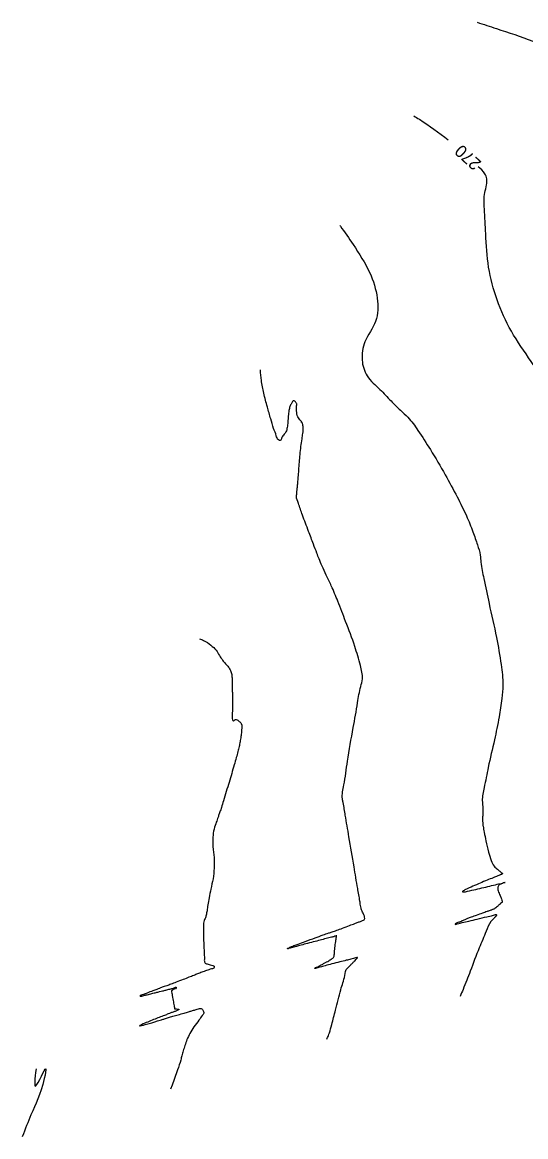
# Model space of a CAD drawing. Extents: x -478102 to -473059, y -1117705 to -1114104.
# Drawn here: x -478101.7 to -477938.7, y -1117550.7 to -1117189.8 of the extents above; entities that cross this region are included whole.
import ezdxf

# ---------------------------------------------------------------- set-up
doc = ezdxf.new("R2010")
doc.units = 0
for name, color, linetype in [('Vrstevnice_hlavni', 7, 'Continuous'), ('Vrstevnice_popis', 7, 'Continuous'), ('Vrstevnice_vedlejsi', 7, 'Continuous')]:
    doc.layers.add(name, color=color, linetype=linetype)

msp = doc.modelspace()

# ---------------------------------------------------------------- linework, layer by layer
at = {"layer": 'Vrstevnice_hlavni'}
for points in [[(-477974.913, -1117220.071), (-477973.154, -1117221.178), (-477963.793, -1117227.865)], [(-477911.583, -1117449.228), (-477910.477, -1117445.772), (-477910.019, -1117444.447), (-477909.658, -1117443.526), (-477909.392, -1117443.009), (-477909.13, -1117442.624), (-477908.873, -1117442.372), (-477908.621, -1117442.252), (-477908.32, -1117440.177), (-477907.97, -1117436.148), (-477907.573, -1117430.164), (-477907.024, -1117423.487), (-477906.324, -1117416.119), (-477905.473, -1117408.06), (-477904.757, -1117400.83), (-477904.178, -1117394.43), (-477903.734, -1117388.86), (-477903.684, -1117382.559), (-477904.026, -1117375.527), (-477904.762, -1117367.764), (-477905.619, -1117361.343), (-477906.598, -1117356.266), (-477907.698, -1117352.532), (-477909.68, -1117347.951), (-477912.544, -1117342.521), (-477916.289, -1117336.243), (-477919.3, -1117330.94), (-477921.576, -1117326.612), (-477923.119, -1117323.257), (-477924.801, -1117319.855), (-477926.621, -1117316.406), (-477928.579, -1117312.91), (-477932.023, -1117307.311), (-477936.953, -1117299.609), (-477943.367, -1117289.805), (-477947.957, -1117279.645), (-477950.723, -1117269.132), (-477951.664, -1117258.263), (-477952.088, -1117250.196), (-477951.996, -1117244.93), (-477951.386, -1117242.465), (-477951.356, -1117240.437), (-477951.906, -1117238.846), (-477954.163, -1117236.539)]]:
    msp.add_spline(points, degree=3, dxfattribs=at)
at = {"layer": 'Vrstevnice_vedlejsi'}
msp.add_line((-478053.213, -1117534.03), (-478053.687, -1117535.309), dxfattribs=at)
for points in [[(-477954.454, -1117189.777), (-477948.211, -1117191.791), (-477936.422, -1117195.896), (-477928.048, -1117199.17), (-477923.089, -1117201.613), (-477921.545, -1117203.226), (-477918.986, -1117206.68), (-477915.414, -1117211.974), (-477910.828, -1117219.108), (-477907.487, -1117225.392), (-477905.391, -1117230.828), (-477904.539, -1117235.414), (-477904.79, -1117241.921), (-477906.143, -1117250.35), (-477908.597, -1117260.701), (-477910.296, -1117268.595), (-477911.24, -1117274.034), (-477911.429, -1117277.017), (-477909.757, -1117280.714), (-477906.224, -1117285.125), (-477900.83, -1117290.251), (-477895.519, -1117295.224), (-477890.29, -1117300.046), (-477885.145, -1117304.716), (-477880.549, -1117309.008), (-477876.503, -1117312.924), (-477873.006, -1117316.462), (-477870.428, -1117320.233), (-477868.77, -1117324.236), (-477868.031, -1117328.472), (-477866.681, -1117334.328), (-477864.72, -1117341.805), (-477862.147, -1117350.902), (-477860.639, -1117359.029), (-477860.198, -1117366.184), (-477860.823, -1117372.368), (-477861.454, -1117378.874), (-477862.091, -1117385.702), (-477862.734, -1117392.851), (-477863.037, -1117399.446), (-477862.998, -1117405.488), (-477862.617, -1117410.976), (-477862.345, -1117415.865), (-477862.18, -1117420.156), (-477862.122, -1117423.848), (-477862.019, -1117426.978), (-477861.868, -1117429.545), (-477861.672, -1117431.549), (-477861.33, -1117433.074), (-477860.844, -1117434.119), (-477860.213, -1117434.684), (-477859.737, -1117435.119), (-477859.415, -1117435.425), (-477859.249, -1117435.601), (-477859.805, -1117436.002), (-477861.085, -1117436.629), (-477863.088, -1117437.481), (-477864.741, -1117438.177), (-477866.043, -1117438.717), (-477866.996, -1117439.1), (-477868.438, -1117439.714), (-477870.371, -1117440.557), (-477872.793, -1117441.629), (-477874.666, -1117442.446), (-477875.99, -1117443.008), (-477876.763, -1117443.314), (-477877.55, -1117443.633), (-477878.351, -1117443.965), (-477879.164, -1117444.31), (-477879.357, -1117444.451), (-477878.928, -1117444.387), (-477877.878, -1117444.12), (-477877.052, -1117443.907), (-477876.449, -1117443.747), (-477876.07, -1117443.642), (-477874.783, -1117443.296), (-477872.588, -1117442.71)], [(-477998.879, -1117255.557), (-477998.727, -1117255.77), (-477994.613, -1117261.766), (-477989.226, -1117270.883), (-477986.788, -1117279.171), (-477987.299, -1117286.631), (-477990.759, -1117293.261), (-477991.682, -1117299.15), (-477990.068, -1117304.296), (-477985.915, -1117308.701), (-477982.328, -1117312.403), (-477979.306, -1117315.404), (-477976.849, -1117317.702), (-477973.612, -1117321.957), (-477969.594, -1117328.168), (-477964.797, -1117336.336), (-477960.899, -1117343.504), (-477957.9, -1117349.67), (-477955.8, -1117354.835), (-477954.323, -1117359.055), (-477953.469, -1117362.331), (-477953.239, -1117364.661), (-477952.282, -1117369.883), (-477950.598, -1117377.995), (-477948.188, -1117388.997), (-477946.693, -1117397.801), (-477946.113, -1117404.405), (-477946.449, -1117408.81), (-477947.352, -1117414.723), (-477948.823, -1117422.144), (-477950.861, -1117431.072), (-477952.177, -1117437.645), (-477952.771, -1117441.863), (-477952.644, -1117443.726), (-477952.589, -1117445.223), (-477952.606, -1117446.354), (-477952.696, -1117447.119), (-477952.711, -1117448.007), (-477952.649, -1117449.018), (-477952.512, -1117450.153), (-477952.156, -1117452.114), (-477951.583, -1117454.901), (-477950.791, -1117458.515), (-477949.91, -1117461.246), (-477948.939, -1117463.094), (-477947.878, -1117464.059), (-477947.136, -1117464.728), (-477946.712, -1117465.101), (-477946.606, -1117465.179), (-477946.495, -1117465.26), (-477946.379, -1117465.346), (-477946.257, -1117465.436), (-477946.233, -1117465.524), (-477946.307, -1117465.609), (-477946.478, -1117465.691), (-477946.651, -1117465.772), (-477946.824, -1117465.851), (-477946.999, -1117465.928), (-477947.792, -1117466.25), (-477949.203, -1117466.816), (-477951.232, -1117467.627), (-477953.439, -1117468.556), (-477955.824, -1117469.604), (-477958.387, -1117470.771), (-477959.194, -1117471.349), (-477958.243, -1117471.339)], [(-477991.867, -1117477.245), (-477991.928, -1117477.172), (-477992.04, -1117476.677), (-477992.202, -1117475.763), (-477992.413, -1117474.428), (-477993.107, -1117470.277), (-477994.282, -1117463.311), (-477995.94, -1117453.528), (-477997.123, -1117446.591), (-477997.83, -1117442.497), (-477998.062, -1117441.249), (-477997.593, -1117436.785), (-477996.423, -1117429.106), (-477994.553, -1117418.212), (-477993.126, -1117410.136), (-477992.143, -1117404.879), (-477991.604, -1117402.439), (-477992.237, -1117398.118), (-477994.043, -1117391.915), (-477997.021, -1117383.831), (-477999.558, -1117377.283), (-478001.654, -1117372.273), (-478003.307, -1117368.799), (-478004.636, -1117365.887), (-478005.64, -1117363.535), (-478006.319, -1117361.745), (-478007.439, -1117358.786), (-478009, -1117354.657), (-478011.003, -1117349.359), (-478012.316, -1117345.574), (-478012.939, -1117343.304), (-478012.872, -1117342.547), (-478012.777, -1117341.561), (-478012.655, -1117340.344), (-478012.505, -1117338.897), (-478012.348, -1117337.07), (-478012.182, -1117334.863), (-478012.009, -1117332.276), (-478011.775, -1117329.718), (-478011.478, -1117327.189), (-478011.12, -1117324.688), (-478010.876, -1117322.931), (-478010.745, -1117321.917), (-478010.728, -1117321.646), (-478010.753, -1117321.243), (-478010.821, -1117320.708), (-478010.93, -1117320.041), (-478011.029, -1117319.606), (-478011.115, -1117319.402), (-478011.19, -1117319.431), (-478011.241, -1117319.41), (-478011.268, -1117319.341), (-478011.271, -1117319.224), (-478011.447, -1117318.941), (-478011.795, -1117318.493), (-478012.316, -1117317.879), (-478012.672, -1117317.097), (-478012.863, -1117316.147), (-478012.89, -1117315.028), (-478012.892, -1117314.215), (-478012.869, -1117313.71), (-478012.821, -1117313.512), (-478012.909, -1117313.243), (-478013.131, -1117312.902), (-478013.489, -1117312.491), (-478013.809, -1117312.342), (-478014.093, -1117312.455), (-478014.34, -1117312.83), (-478014.581, -1117313.247), (-478014.817, -1117313.705), (-478015.046, -1117314.206), (-478015.238, -1117314.822), (-478015.392, -1117315.554), (-478015.508, -1117316.401), (-478015.602, -1117317.301), (-478015.672, -1117318.253), (-478015.72, -1117319.257), (-478015.808, -1117320.173), (-478015.935, -1117321.003), (-478016.103, -1117321.746), (-478016.33, -1117322.362), (-478016.618, -1117322.853), (-478016.967, -1117323.218), (-478017.343, -1117323.742), (-478017.748, -1117324.426), (-478018.182, -1117325.269), (-478018.755, -1117325.029), (-478019.468, -1117323.706), (-478020.32, -1117321.3), (-478021.282, -1117318.195), (-478022.355, -1117314.389), (-478023.538, -1117309.884), (-478024.297, -1117305.737), (-478024.625, -1117302.334)], [(-478044.323, -1117389.497), (-478042.996, -1117389.964), (-478040.645, -1117391.528), (-478038.938, -1117393.157), (-478037.876, -1117394.852), (-478036.855, -1117396.325), (-478035.874, -1117397.575), (-478034.935, -1117398.602), (-478034.275, -1117399.76), (-478033.895, -1117401.05), (-478033.795, -1117402.47), (-478033.734, -1117403.559), (-478033.712, -1117404.316), (-478033.729, -1117404.741), (-478033.725, -1117405.596), (-478033.699, -1117406.882), (-478033.652, -1117408.598), (-478033.647, -1117410.423), (-478033.685, -1117412.357), (-478033.765, -1117414.398), (-478033.662, -1117415.636), (-478033.377, -1117416.07), (-478032.909, -1117415.7), (-478032.433, -1117415.597), (-478031.948, -1117415.763), (-478031.455, -1117416.196), (-478031.095, -1117416.556), (-478030.869, -1117416.842), (-478030.778, -1117417.054), (-478030.702, -1117417.25), (-478030.642, -1117417.43), (-478030.599, -1117417.594), (-478030.633, -1117418.265), (-478030.746, -1117419.442), (-478030.936, -1117421.127), (-478031.189, -1117422.771), (-478031.506, -1117424.376), (-478031.885, -1117425.94), (-478032.413, -1117427.911), (-478033.089, -1117430.288), (-478033.913, -1117433.072), (-478034.768, -1117435.929), (-478035.655, -1117438.861), (-478036.572, -1117441.865), (-478037.258, -1117444.074), (-478037.711, -1117445.486), (-478037.933, -1117446.102), (-478038.323, -1117447.233), (-478038.882, -1117448.881), (-478039.609, -1117451.044), (-478039.974, -1117453.668), (-478039.978, -1117456.752), (-478039.62, -1117460.297), (-478039.614, -1117463.766), (-478039.96, -1117467.16), (-478040.659, -1117470.478), (-478041.215, -1117473.309), (-478041.627, -1117475.65), (-478041.895, -1117477.504), (-478042.188, -1117478.963), (-478042.508, -1117480.028), (-478042.852, -1117480.698), (-478043.034, -1117482.402), (-478043.052, -1117485.14), (-478042.907, -1117488.911), (-478042.811, -1117491.623), (-478042.763, -1117493.276), (-478042.764, -1117493.87), (-478042.605, -1117494.312), (-478042.286, -1117494.604), (-478041.807, -1117494.745), (-478041.205, -1117494.94), (-478040.478, -1117495.19), (-478039.628, -1117495.494), (-478039.61, -1117495.88), (-478040.424, -1117496.348), (-478042.07, -1117496.896), (-478043.579, -1117497.431), (-478044.951, -1117497.952), (-478046.187, -1117498.458), (-478047.753, -1117499.08), (-478049.649, -1117499.817), (-478051.876, -1117500.669), (-478053.635, -1117501.33), (-478054.925, -1117501.799), (-478055.746, -1117502.077), (-478056.417, -1117502.312), (-478056.936, -1117502.505), (-478057.304, -1117502.655), (-478058.15, -1117502.98), (-478059.473, -1117503.48)], [(-477958.243, -1117471.339), (-477955.536, -1117470.741), (-477952.915, -1117470.142), (-477950.378, -1117469.541), (-477947.927, -1117468.939), (-477946.283, -1117468.538), (-477945.445, -1117468.338), (-477945.414, -1117468.339), (-477945.712, -1117468.473), (-477946.339, -1117468.742), (-477947.296, -1117469.144), (-477947.728, -1117469.923), (-477947.635, -1117471.079), (-477947.017, -1117472.611), (-477946.597, -1117473.709), (-477946.375, -1117474.371), (-477946.35, -1117474.598), (-477946.374, -1117474.773), (-477946.445, -1117474.897), (-477946.564, -1117474.97), (-477946.676, -1117475.037), (-477946.782, -1117475.1), (-477946.881, -1117475.157), (-477946.943, -1117475.205), (-477946.968, -1117475.243), (-477946.957, -1117475.27), (-477947.157, -1117475.466), (-477947.57, -1117475.831), (-477948.194, -1117476.365), (-477948.672, -1117476.747), (-477949.004, -1117476.976), (-477949.191, -1117477.054), (-477949.465, -1117477.156), (-477949.826, -1117477.283), (-477950.274, -1117477.435), (-477951.24, -1117477.772), (-477952.723, -1117478.294), (-477954.724, -1117479.003), (-477956.35, -1117479.597), (-477957.602, -1117480.076), (-477958.479, -1117480.441), (-477959.413, -1117480.834), (-477960.402, -1117481.255), (-477961.448, -1117481.704), (-477961.603, -1117481.871), (-477960.869, -1117481.757), (-477959.244, -1117481.361), (-477957.105, -1117480.843), (-477954.45, -1117480.202), (-477951.281, -1117479.438), (-477949.178, -1117478.982), (-477948.142, -1117478.834), (-477948.174, -1117478.994), (-477948.491, -1117479.411), (-477949.094, -1117480.085), (-477949.982, -1117481.016), (-477951.543, -1117484.163), (-477953.776, -1117489.526), (-477956.682, -1117497.105), (-477959.001, -1117502.97), (-477959.941, -1117505.268)], [(-478003.144, -1117519.112), (-478003.132, -1117519.091), (-478002.849, -1117518.531), (-478002.564, -1117517.866), (-478002.277, -1117517.095), (-478001.519, -1117514.373), (-478000.289, -1117509.7), (-477998.587, -1117503.075), (-477997.307, -1117498.528), (-477996.448, -1117496.058), (-477996.011, -1117495.664), (-477995.494, -1117495.164), (-477994.897, -1117494.557), (-477994.22, -1117493.842), (-477993.709, -1117493.305), (-477993.364, -1117492.946), (-477993.185, -1117492.764), (-477993.124, -1117492.659), (-477993.181, -1117492.63), (-477993.356, -1117492.676), (-477993.771, -1117492.785), (-477994.426, -1117492.954), (-477995.322, -1117493.185), (-477996.795, -1117493.562), (-477998.846, -1117494.085), (-478001.473, -1117494.753), (-478003.611, -1117495.312), (-478005.26, -1117495.76), (-478006.419, -1117496.098), (-478006.996, -1117496.219), (-478006.993, -1117496.123), (-478006.408, -1117495.809), (-478005.709, -1117495.438), (-478004.894, -1117495.01), (-478003.965, -1117494.524), (-478003.169, -1117494.089), (-478002.505, -1117493.706), (-478001.974, -1117493.373), (-478001.536, -1117493.087), (-478001.191, -1117492.847), (-478000.937, -1117492.652), (-478000.751, -1117492.194), (-478000.632, -1117491.473), (-478000.581, -1117490.488), (-478000.498, -1117489.492), (-478000.385, -1117488.485), (-478000.24, -1117487.467), (-478000.128, -1117486.703), (-478000.048, -1117486.194), (-478000.001, -1117485.94), (-477999.965, -1117485.766), (-477999.941, -1117485.673), (-477999.928, -1117485.661), (-478000.489, -1117485.799), (-478001.623, -1117486.089), (-478003.33, -1117486.529), (-478005.282, -1117487.037), (-478007.479, -1117487.611), (-478009.922, -1117488.252), (-478011.864, -1117488.767), (-478013.305, -1117489.157), (-478014.246, -1117489.421), (-478014.977, -1117489.616), (-478015.498, -1117489.744), (-478015.809, -1117489.803), (-478015.836, -1117489.758), (-478015.578, -1117489.608), (-478015.036, -1117489.355), (-478014.549, -1117489.136), (-478014.118, -1117488.952), (-478013.741, -1117488.803), (-478012.405, -1117488.306), (-478010.108, -1117487.462), (-478006.85, -1117486.27), (-478004.315, -1117485.357), (-478002.502, -1117484.722), (-478001.412, -1117484.367), (-477999.922, -1117483.843), (-477998.032, -1117483.15), (-477995.742, -1117482.288), (-477994.054, -1117481.654), (-477992.967, -1117481.248), (-477992.483, -1117481.068), (-477991.998, -1117480.879), (-477991.512, -1117480.68), (-477991.026, -1117480.472), (-477990.843, -1117480.006), (-477990.962, -1117479.282), (-477991.383, -1117478.3), (-477991.685, -1117477.622), (-477991.867, -1117477.245)], [(-478059.473, -1117503.48), (-478061.273, -1117504.155), (-478062.505, -1117504.62), (-478063.169, -1117504.874), (-478063.265, -1117504.919), (-478063.348, -1117504.951), (-478063.419, -1117504.972), (-478063.477, -1117504.981), (-478063.524, -1117504.995), (-478063.56, -1117505.013), (-478063.585, -1117505.036), (-478063.595, -1117505.066), (-478063.591, -1117505.103), (-478063.57, -1117505.147), (-478063.526, -1117505.177), (-478063.458, -1117505.194), (-478063.366, -1117505.198), (-478063.254, -1117505.189), (-478063.124, -1117505.167), (-478062.974, -1117505.132), (-478062.359, -1117504.978), (-478061.278, -1117504.705), (-478059.732, -1117504.311), (-478058.385, -1117503.975), (-478057.239, -1117503.697), (-478056.293, -1117503.477), (-478055.194, -1117503.201), (-478053.942, -1117502.871), (-478052.538, -1117502.485), (-478051.841, -1117502.369), (-478051.851, -1117502.521), (-478052.569, -1117502.943), (-478053.063, -1117503.23), (-478053.334, -1117503.384), (-478053.381, -1117503.404), (-478053.347, -1117503.774), (-478053.23, -1117504.495), (-478053.03, -1117505.565), (-478052.853, -1117506.552), (-478052.698, -1117507.454), (-478052.564, -1117508.272), (-478052.466, -1117508.842), (-478052.403, -1117509.165), (-478052.374, -1117509.239), (-478052.188, -1117509.294), (-478051.845, -1117509.328), (-478051.344, -1117509.342), (-478051.064, -1117509.394), (-478051.005, -1117509.486), (-478051.168, -1117509.616), (-478051.427, -1117509.761), (-478051.782, -1117509.921), (-478052.234, -1117510.097), (-478052.683, -1117510.269), (-478053.128, -1117510.439), (-478053.57, -1117510.606), (-478054.428, -1117510.934), (-478055.701, -1117511.423), (-478057.392, -1117512.072), (-478059.194, -1117512.787), (-478061.11, -1117513.568), (-478063.138, -1117514.415), (-478063.798, -1117514.79), (-478063.089, -1117514.692), (-478061.01, -1117514.123), (-478059.39, -1117513.667), (-478058.228, -1117513.324), (-478057.524, -1117513.095), (-478056.651, -1117512.821), (-478055.61, -1117512.502), (-478054.401, -1117512.139), (-478052.948, -1117511.707), (-478051.253, -1117511.208), (-478049.313, -1117510.64), (-478047.84, -1117510.209), (-478046.831, -1117509.914), (-478046.288, -1117509.755), (-478045.694, -1117509.584), (-478045.048, -1117509.401), (-478044.351, -1117509.205), (-478043.802, -1117509.228), (-478043.401, -1117509.471), (-478043.149, -1117509.932), (-478042.982, -1117510.283), (-478042.902, -1117510.524), (-478042.908, -1117510.653), (-478043.448, -1117511.466), (-478044.521, -1117512.962), (-478046.128, -1117515.142), (-478047.422, -1117517.235), (-478048.402, -1117519.244), (-478049.068, -1117521.166), (-478049.621, -1117522.911), (-478050.059, -1117524.479), (-478050.382, -1117525.869), (-478051.434, -1117529.052), (-478053.213, -1117534.03)], [(-478097.26, -1117528.759), (-478097.327, -1117534.259), (-478094.062, -1117528.696), (-478094.59, -1117531.824), (-478098.909, -1117543.642), (-478101.702, -1117550.697)]]:
    msp.add_spline(points, degree=3, dxfattribs=at)

# ---------------------------------------------------------------- texts
at = {"layer": 'Vrstevnice_popis'}
msp.add_text(' 270 ', height=4, rotation=137.98337, dxfattribs=at).set_placement((-477951.692, -1117236.071))

doc.saveas('drawing.dxf')
